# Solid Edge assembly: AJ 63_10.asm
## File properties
Title: Zylinder
Author: ahadarics
Template: iso metric assembly.asm
Last saved by: ahadarics
Revision: 3
Application: Solid Edge
Username: ahadarics
Dokumentum tartalom típus: 1
Document Number: AJ 63/10
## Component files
Kit.par
Kolbenstange.par
Profilrohr.par
Mutter_1.par
Mutter_2.par
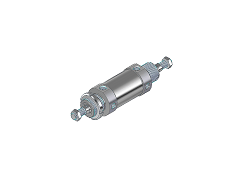
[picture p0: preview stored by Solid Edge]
